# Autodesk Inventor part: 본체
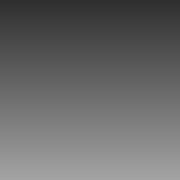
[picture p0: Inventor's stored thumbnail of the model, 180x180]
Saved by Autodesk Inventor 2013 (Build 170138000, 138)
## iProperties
Created: 2018-10
Part Number: 본체
Material: Generic
Document SubType Name: Modeling
Designer: Administrator
Density: 1 g/cm^3
Author: Administrator
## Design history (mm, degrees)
